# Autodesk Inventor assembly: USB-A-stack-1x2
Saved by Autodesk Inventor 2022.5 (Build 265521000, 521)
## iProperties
Created: 2024-12
Part Number: USB-A-stack-1x2
Document SubType Name: Assembly
Designer: AdminForWorker
Title: USB-A-stack-1x2 v1
Author: AdminForWorker
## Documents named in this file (4)
- c:\worker\convert-fusion-r05-cosv3\tmp\job-1\35\temp\files\545dca92-a972-481a-9197-dd1a1176500e\USB-A-stack-1x2 v1.iam
- c:\worker\convert-fusion-r05-cosv3\tmp\job-1\35\temp\files\545dca92-a972-481a-9197-dd1a1176500e\shell.iam
- c:\worker\convert-fusion-r05-cosv3\tmp\job-1\35\temp\files\545dca92-a972-481a-9197-dd1a1176500e\Component4.iam
- c:\worker\convert-fusion-r05-cosv3\tmp\job-1\35\temp\files\545dca92-a972-481a-9197-dd1a1176500e\leads_1.iam
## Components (3 placed, 3 different names)
1. shell:1 [sub-assembly]
2. Component4:1 [sub-assembly]
3. leads:1 [sub-assembly]
